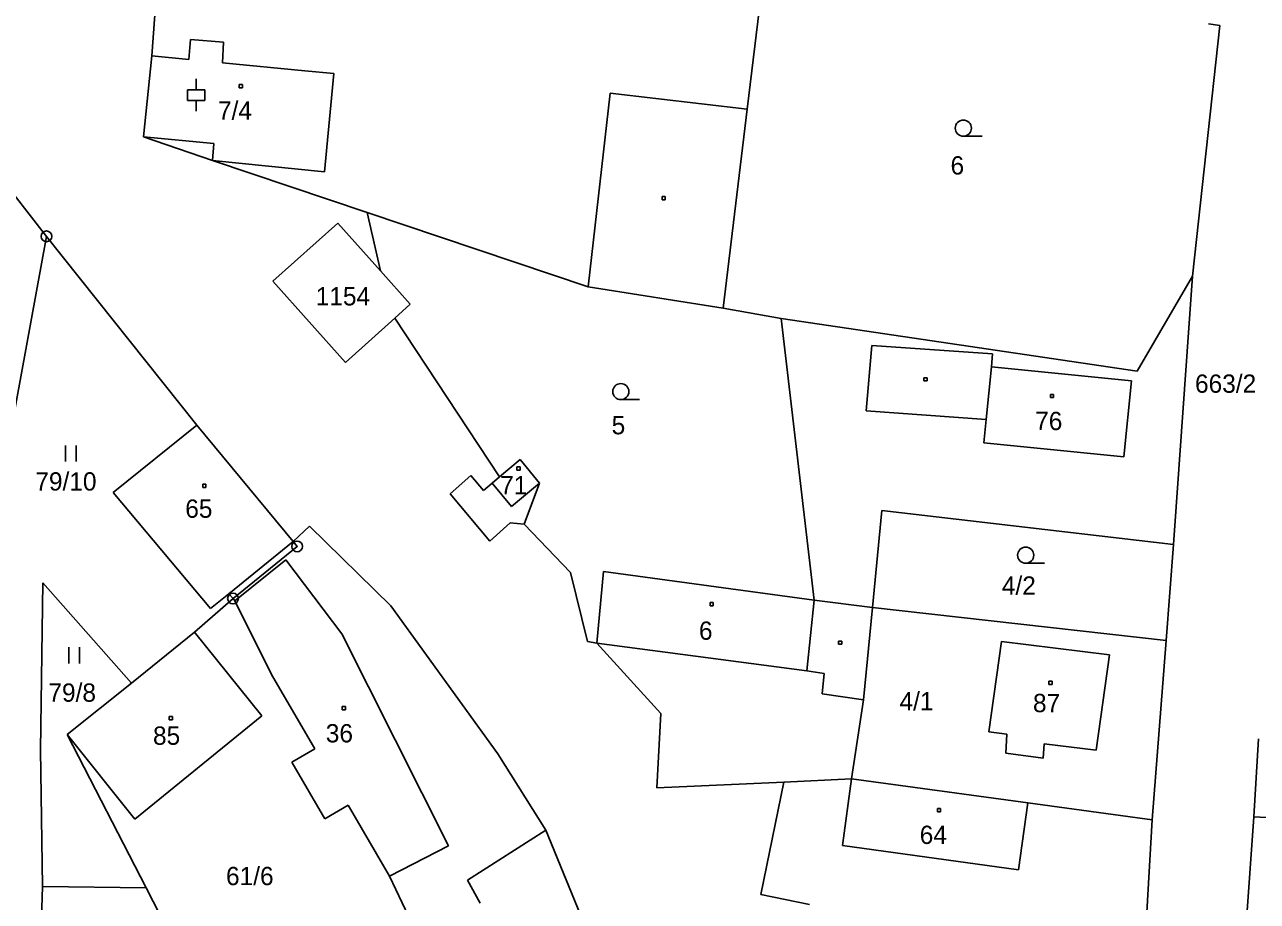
# Model space of a CAD drawing. Extents: x -794142 to -791199, y -1109267 to -1105626.
# Drawn here: x -793459.6 to -793345, y -1107931.8 to -1107850.3 of the extents above; entities that cross this region are included whole.
import ezdxf

# ---------------------------------------------------------------- set-up
doc = ezdxf.new("R2010")
doc.units = 0
for name, color, linetype in [('Vrstva 1', 7, 'Continuous'), ('Vrstva 14', 7, 'Continuous'), ('Vrstva 15', 7, 'Continuous'), ('Vrstva 2', 7, 'Continuous'), ('Vrstva 23', 7, 'Continuous'), ('Vrstva 25', 7, 'Continuous'), ('Vrstva 28', 7, 'Continuous')]:
    doc.layers.add(name, color=color, linetype=linetype)

msp = doc.modelspace()

# ---------------------------------------------------------------- linework, layer by layer
at = {"layer": 'Vrstva 1'}
for p, q in [((-793392.43, -1107858.15), (-793390.61, -1107843.24)), ((-793447.26, -1107846.09), (-793447.78, -1107853.18)), ((-793348.49, -1107850.37), (-793351.04, -1107873.67)), ((-793349.56, -1107850.19), (-793348.49, -1107850.37)), ((-793444.35, -1107853.51), (-793444.18, -1107851.67)), ((-793444.18, -1107851.67), (-793441.12, -1107851.92)), ((-793441.12, -1107851.92), (-793441.21, -1107853.82)), ((-793457.57, -1107869.96), (-793470.25, -1107853.7)), ((-793448.56, -1107860.72), (-793447.78, -1107853.18)), ((-793447.78, -1107853.18), (-793444.35, -1107853.51)), ((-793441.21, -1107853.82), (-793433.55, -1107854.56)), ((-793433.55, -1107854.56), (-793430.85, -1107854.82)), ((-793430.85, -1107854.82), (-793431.73, -1107863.96)), ((-793394.68, -1107876.63), (-793392.43, -1107858.15)), ((-793442.13, -1107862.91), (-793448.56, -1107860.72)), ((-793442.13, -1107862.91), (-793427.77, -1107867.73)), ((-793431.73, -1107863.96), (-793442.13, -1107862.91)), ((-793407.22, -1107874.65), (-793427.77, -1107867.73)), ((-793427.77, -1107867.73), (-793426.53, -1107873.16)), ((-793436.53, -1107874.14), (-793430.49, -1107868.73)), ((-793430.49, -1107868.73), (-793426.53, -1107873.16)), ((-793457.57, -1107869.96), (-793461.81, -1107893.18)), ((-793457.57, -1107869.96), (-793443.59, -1107887.52)), ((-793426.53, -1107873.16), (-793423.75, -1107876.26)), ((-793429.79, -1107881.67), (-793436.53, -1107874.14)), ((-793351.04, -1107873.67), (-793356.17, -1107882.49)), ((-793351.04, -1107873.67), (-793352.8, -1107898.61)), ((-793407.22, -1107874.65), (-793394.68, -1107876.63)), ((-793425.2, -1107877.56), (-793423.75, -1107876.26)), ((-793389.28, -1107877.58), (-793394.68, -1107876.63)), ((-793429.79, -1107881.67), (-793425.2, -1107877.56)), ((-793415.46, -1107892.31), (-793425.2, -1107877.56)), ((-793356.17, -1107882.49), (-793389.28, -1107877.58)), ((-793389.28, -1107877.58), (-793386.19, -1107903.78)), ((-793451.37, -1107893.78), (-793443.59, -1107887.52)), ((-793443.59, -1107887.52), (-793434.65, -1107898.31)), ((-793415.46, -1107892.31), (-793413.55, -1107890.7)), ((-793413.55, -1107890.7), (-793411.73, -1107892.89)), ((-793418.12, -1107892.18), (-793420.03, -1107893.9)), ((-793416.96, -1107893.58), (-793418.12, -1107892.18)), ((-793416.15, -1107892.9), (-793416.96, -1107893.58)), ((-793416.15, -1107892.9), (-793415.46, -1107892.31)), ((-793413.18, -1107896.72), (-793411.73, -1107892.89)), ((-793442.31, -1107904.55), (-793451.37, -1107893.78)), ((-793420.03, -1107893.9), (-793416.36, -1107898.28)), ((-793379.9, -1107895.44), (-793380.79, -1107904.45)), ((-793352.8, -1107898.61), (-793379.9, -1107895.44)), ((-793434.65, -1107898.31), (-793433.12, -1107896.9)), ((-793433.12, -1107896.9), (-793425.55, -1107904.32)), ((-793414.46, -1107896.6), (-793416.36, -1107898.28)), ((-793414.46, -1107896.6), (-793413.18, -1107896.72)), ((-793413.18, -1107896.72), (-793408.86, -1107901.21)), ((-793434.65, -1107898.31), (-793434.27, -1107898.78)), ((-793353.49, -1107907.52), (-793352.8, -1107898.61)), ((-793434.27, -1107898.78), (-793440.23, -1107903.63)), ((-793408.86, -1107901.21), (-793407.27, -1107907.63)), ((-793406.4, -1107907.76), (-793405.79, -1107901.11)), ((-793386.19, -1107903.78), (-793405.79, -1107901.11)), ((-793458.14, -1107917.7), (-793457.9, -1107902.18)), ((-793449.68, -1107911.48), (-793457.9, -1107902.18)), ((-793440.63, -1107903.18), (-793442.31, -1107904.55)), ((-793440.23, -1107903.63), (-793440.63, -1107903.18)), ((-793443.8, -1107906.75), (-793440.23, -1107903.63)), ((-793440.23, -1107903.63), (-793440.06, -1107903.85)), ((-793436.67, -1107910.69), (-793440.06, -1107903.85)), ((-793415.6, -1107918.06), (-793425.55, -1107904.32)), ((-793380.79, -1107904.45), (-793386.19, -1107903.78)), ((-793380.79, -1107904.45), (-793381.63, -1107913.03)), ((-793380.79, -1107904.45), (-793353.49, -1107907.52)), ((-793449.68, -1107911.48), (-793443.8, -1107906.75)), ((-793437.56, -1107914.53), (-793443.8, -1107906.75)), ((-793407.27, -1107907.63), (-793406.4, -1107907.76)), ((-793406.4, -1107907.76), (-793400.47, -1107914.3)), ((-793368.79, -1107907.62), (-793369.96, -1107916.02)), ((-793358.76, -1107908.86), (-793368.79, -1107907.62)), ((-793354.79, -1107924.2), (-793353.49, -1107907.52)), ((-793358.76, -1107908.86), (-793359.99, -1107917.72)), ((-793432.63, -1107917.59), (-793436.67, -1107910.69)), ((-793455.65, -1107916.27), (-793449.68, -1107911.48)), ((-793381.63, -1107913.03), (-793382.75, -1107920.4)), ((-793449.35, -1107924.15), (-793437.56, -1107914.53)), ((-793400.47, -1107914.3), (-793400.82, -1107921.22)), ((-793455.65, -1107916.27), (-793449.35, -1107924.15)), ((-793448.32, -1107930.51), (-793455.65, -1107916.27)), ((-793369.96, -1107916.02), (-793368.28, -1107916.22)), ((-793368.28, -1107916.22), (-793368.39, -1107918)), ((-793344.89, -1107916.66), (-793345.34, -1107923.91)), ((-793457.93, -1107930.38), (-793458.14, -1107917.7)), ((-793434.77, -1107918.84), (-793432.63, -1107917.59)), ((-793411.16, -1107925.15), (-793415.6, -1107918.06)), ((-793368.39, -1107918), (-793364.93, -1107918.46)), ((-793364.93, -1107918.46), (-793364.83, -1107917.14)), ((-793364.83, -1107917.14), (-793359.99, -1107917.72)), ((-793431.69, -1107924.11), (-793434.77, -1107918.84)), ((-793389.03, -1107920.69), (-793382.75, -1107920.4)), ((-793382.75, -1107920.4), (-793366.35, -1107922.62)), ((-793400.82, -1107921.22), (-793389.03, -1107920.69)), ((-793389.03, -1107920.69), (-793391.17, -1107931.15)), ((-793366.35, -1107922.62), (-793354.79, -1107924.2)), ((-793429.54, -1107922.85), (-793431.69, -1107924.11)), ((-793425.68, -1107929.45), (-793429.54, -1107922.85)), ((-793345.34, -1107923.91), (-793346.26, -1107937.12)), ((-793354.79, -1107924.2), (-793355.57, -1107937.84)), ((-793418.43, -1107929.8), (-793411.16, -1107925.15)), ((-793400.69, -1107950.63), (-793411.16, -1107925.15)), ((-793425.68, -1107929.45), (-793423.1, -1107934.86)), ((-793457.93, -1107930.38), (-793458.47, -1107946.04)), ((-793448.32, -1107930.51), (-793457.93, -1107930.38)), ((-793441.86, -1107943.04), (-793448.32, -1107930.51)), ((-793417.25, -1107931.93), (-793418.43, -1107929.8)), ((-793391.17, -1107931.15), (-793386.63, -1107932.07))]:
    msp.add_line(p, q, dxfattribs=at)
at = {"layer": 'Vrstva 2'}
for p, q in [((-793407.22, -1107874.65), (-793405.17, -1107856.64)), ((-793405.17, -1107856.64), (-793392.43, -1107858.15)), ((-793442.03, -1107861.33), (-793448.56, -1107860.72)), ((-793442.13, -1107862.91), (-793442.03, -1107861.33)), ((-793380.85, -1107880.11), (-793381.36, -1107886.17)), ((-793369.63, -1107880.89), (-793380.85, -1107880.11)), ((-793369.71, -1107882.09), (-793369.63, -1107880.89)), ((-793369.71, -1107882.09), (-793370.21, -1107886.97)), ((-793356.71, -1107883.39), (-793369.71, -1107882.09)), ((-793356.71, -1107883.39), (-793357.43, -1107890.46)), ((-793381.36, -1107886.17), (-793370.21, -1107886.97)), ((-793370.21, -1107886.97), (-793370.43, -1107889.16)), ((-793357.43, -1107890.46), (-793370.43, -1107889.16)), ((-793416.15, -1107892.9), (-793414.35, -1107895.07)), ((-793414.35, -1107895.07), (-793411.73, -1107892.89)), ((-793440.63, -1107903.18), (-793434.65, -1107898.31)), ((-793440.06, -1107903.85), (-793435.32, -1107900.04)), ((-793435.32, -1107900.04), (-793430.11, -1107906.91)), ((-793386.19, -1107903.78), (-793386.88, -1107910.36)), ((-793430.11, -1107906.91), (-793420.2, -1107926.62)), ((-793406.4, -1107907.76), (-793386.88, -1107910.36)), ((-793386.88, -1107910.36), (-793385.27, -1107910.59)), ((-793385.46, -1107912.47), (-793385.27, -1107910.59)), ((-793381.63, -1107913.03), (-793385.46, -1107912.47)), ((-793382.75, -1107920.4), (-793383.56, -1107926.57)), ((-793367.22, -1107928.86), (-793366.35, -1107922.62)), ((-793345.34, -1107923.91), (-793334.31, -1107924.58)), ((-793420.2, -1107926.62), (-793425.68, -1107929.45)), ((-793383.56, -1107926.57), (-793367.22, -1107928.86))]:
    msp.add_line(p, q, dxfattribs=at)
at = {"layer": 'Vrstva 23'}
for p, q in [((-793443.65, -1107856.33), (-793443.65, -1107855.33)), ((-793444.45, -1107857.33), (-793444.45, -1107856.33)), ((-793444.45, -1107856.33), (-793442.85, -1107856.33)), ((-793442.85, -1107857.33), (-793444.45, -1107857.33)), ((-793443.65, -1107858.33), (-793443.65, -1107857.33)), ((-793442.85, -1107856.33), (-793442.85, -1107857.33)), ((-793372.34, -1107860.65), (-793370.59, -1107860.65)), ((-793404.18, -1107885.14), (-793402.43, -1107885.14)), ((-793455.8, -1107890.89), (-793455.8, -1107889.39)), ((-793454.8, -1107889.39), (-793454.8, -1107890.89)), ((-793366.54, -1107900.35), (-793364.79, -1107900.35)), ((-793455.49, -1107909.66), (-793455.49, -1107908.16)), ((-793454.49, -1107908.16), (-793454.49, -1107909.66))]:
    msp.add_line(p, q, dxfattribs=at)
for centre in [(-793372.34, -1107859.9), (-793404.18, -1107884.39), (-793366.54, -1107899.6)]:
    msp.add_circle(centre, 0.75, dxfattribs=at)
at = {"layer": 'Vrstva 25'}
for p, q in [((-793439.65, -1107855.84), (-793439.35, -1107855.84)), ((-793439.65, -1107856.14), (-793439.65, -1107855.84)), ((-793439.35, -1107856.14), (-793439.65, -1107856.14)), ((-793439.35, -1107855.84), (-793439.35, -1107856.14)), ((-793400.35, -1107866.25), (-793400.05, -1107866.25)), ((-793400.35, -1107866.55), (-793400.35, -1107866.25)), ((-793400.05, -1107866.55), (-793400.35, -1107866.55)), ((-793400.05, -1107866.25), (-793400.05, -1107866.55)), ((-793376, -1107883.1), (-793375.7, -1107883.1)), ((-793376, -1107883.4), (-793376, -1107883.1)), ((-793375.7, -1107883.4), (-793376, -1107883.4)), ((-793375.7, -1107883.1), (-793375.7, -1107883.4)), ((-793364.25, -1107884.65), (-793363.95, -1107884.65)), ((-793364.25, -1107884.95), (-793364.25, -1107884.65)), ((-793363.95, -1107884.95), (-793364.25, -1107884.95)), ((-793363.95, -1107884.65), (-793363.95, -1107884.95)), ((-793413.84, -1107891.39), (-793413.54, -1107891.39)), ((-793413.84, -1107891.69), (-793413.84, -1107891.39)), ((-793413.54, -1107891.69), (-793413.84, -1107891.69)), ((-793413.54, -1107891.39), (-793413.54, -1107891.69)), ((-793443.05, -1107892.99), (-793442.75, -1107892.99)), ((-793443.05, -1107893.29), (-793443.05, -1107892.99)), ((-793442.75, -1107893.29), (-793443.05, -1107893.29)), ((-793442.75, -1107892.99), (-793442.75, -1107893.29)), ((-793395.88, -1107904.01), (-793395.58, -1107904.01)), ((-793395.88, -1107904.31), (-793395.88, -1107904.01)), ((-793395.58, -1107904.31), (-793395.88, -1107904.31)), ((-793395.58, -1107904.01), (-793395.58, -1107904.31)), ((-793383.93, -1107907.58), (-793383.63, -1107907.58)), ((-793383.93, -1107907.88), (-793383.93, -1107907.58)), ((-793383.63, -1107907.88), (-793383.93, -1107907.88)), ((-793383.63, -1107907.58), (-793383.63, -1107907.88)), ((-793364.39, -1107911.31), (-793364.09, -1107911.31)), ((-793364.39, -1107911.61), (-793364.39, -1107911.31)), ((-793364.09, -1107911.31), (-793364.09, -1107911.61)), ((-793364.09, -1107911.61), (-793364.39, -1107911.61)), ((-793446.17, -1107914.6), (-793445.87, -1107914.6)), ((-793446.17, -1107914.9), (-793446.17, -1107914.6)), ((-793445.87, -1107914.6), (-793445.87, -1107914.9)), ((-793430.08, -1107913.67), (-793429.78, -1107913.67)), ((-793430.08, -1107913.97), (-793430.08, -1107913.67)), ((-793429.78, -1107913.97), (-793430.08, -1107913.97)), ((-793429.78, -1107913.67), (-793429.78, -1107913.97)), ((-793445.87, -1107914.9), (-793446.17, -1107914.9)), ((-793374.75, -1107923.14), (-793374.45, -1107923.14)), ((-793374.75, -1107923.44), (-793374.75, -1107923.14)), ((-793374.45, -1107923.44), (-793374.75, -1107923.44)), ((-793374.45, -1107923.14), (-793374.45, -1107923.44))]:
    msp.add_line(p, q, dxfattribs=at)
at = {"layer": 'Vrstva 28'}
for centre, radius in [((-793457.57, -1107869.96), 0.5), ((-793457.57, -1107869.96), 0.01), ((-793434.27, -1107898.78), 0.5), ((-793434.27, -1107898.78), 0.01), ((-793440.23, -1107903.63), 0.5), ((-793440.23, -1107903.63), 0.01)]:
    msp.add_circle(centre, radius, dxfattribs=at)

# ---------------------------------------------------------------- texts
at = {"layer": 'Vrstva 14'}
for s, p in [('6', (-793373.527, -1107864.21)), ('1154', (-793432.545, -1107876.38)), ('663/2', (-793350.8, -1107884.5)), ('5', (-793405.033, -1107888.36)), ('79/10', (-793458.609, -1107893.59)), ('4/2', (-793368.756, -1107903.27)), ('79/8', (-793457.396, -1107913.22)), ('4/1', (-793378.269, -1107914.02)), ('61/6', (-793440.883, -1107930.27))]:
    msp.add_text(s, height=1.7, dxfattribs=at).set_placement(p)
at = {"layer": 'Vrstva 15'}
for s, p in [('7/4', (-793441.633, -1107859.12)), ('76', (-793365.663, -1107887.97)), ('71', (-793415.397, -1107893.94)), ('65', (-793444.673, -1107896.12)), ('6', (-793396.917, -1107907.46)), ('87', (-793365.863, -1107914.19)), ('85', (-793447.673, -1107917.22)), ('36', (-793431.607, -1107917)), ('64', (-793376.393, -1107926.44))]:
    msp.add_text(s, height=1.7, dxfattribs=at).set_placement(p)

doc.saveas('drawing.dxf')
